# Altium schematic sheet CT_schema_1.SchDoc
size 406 x 198 mm
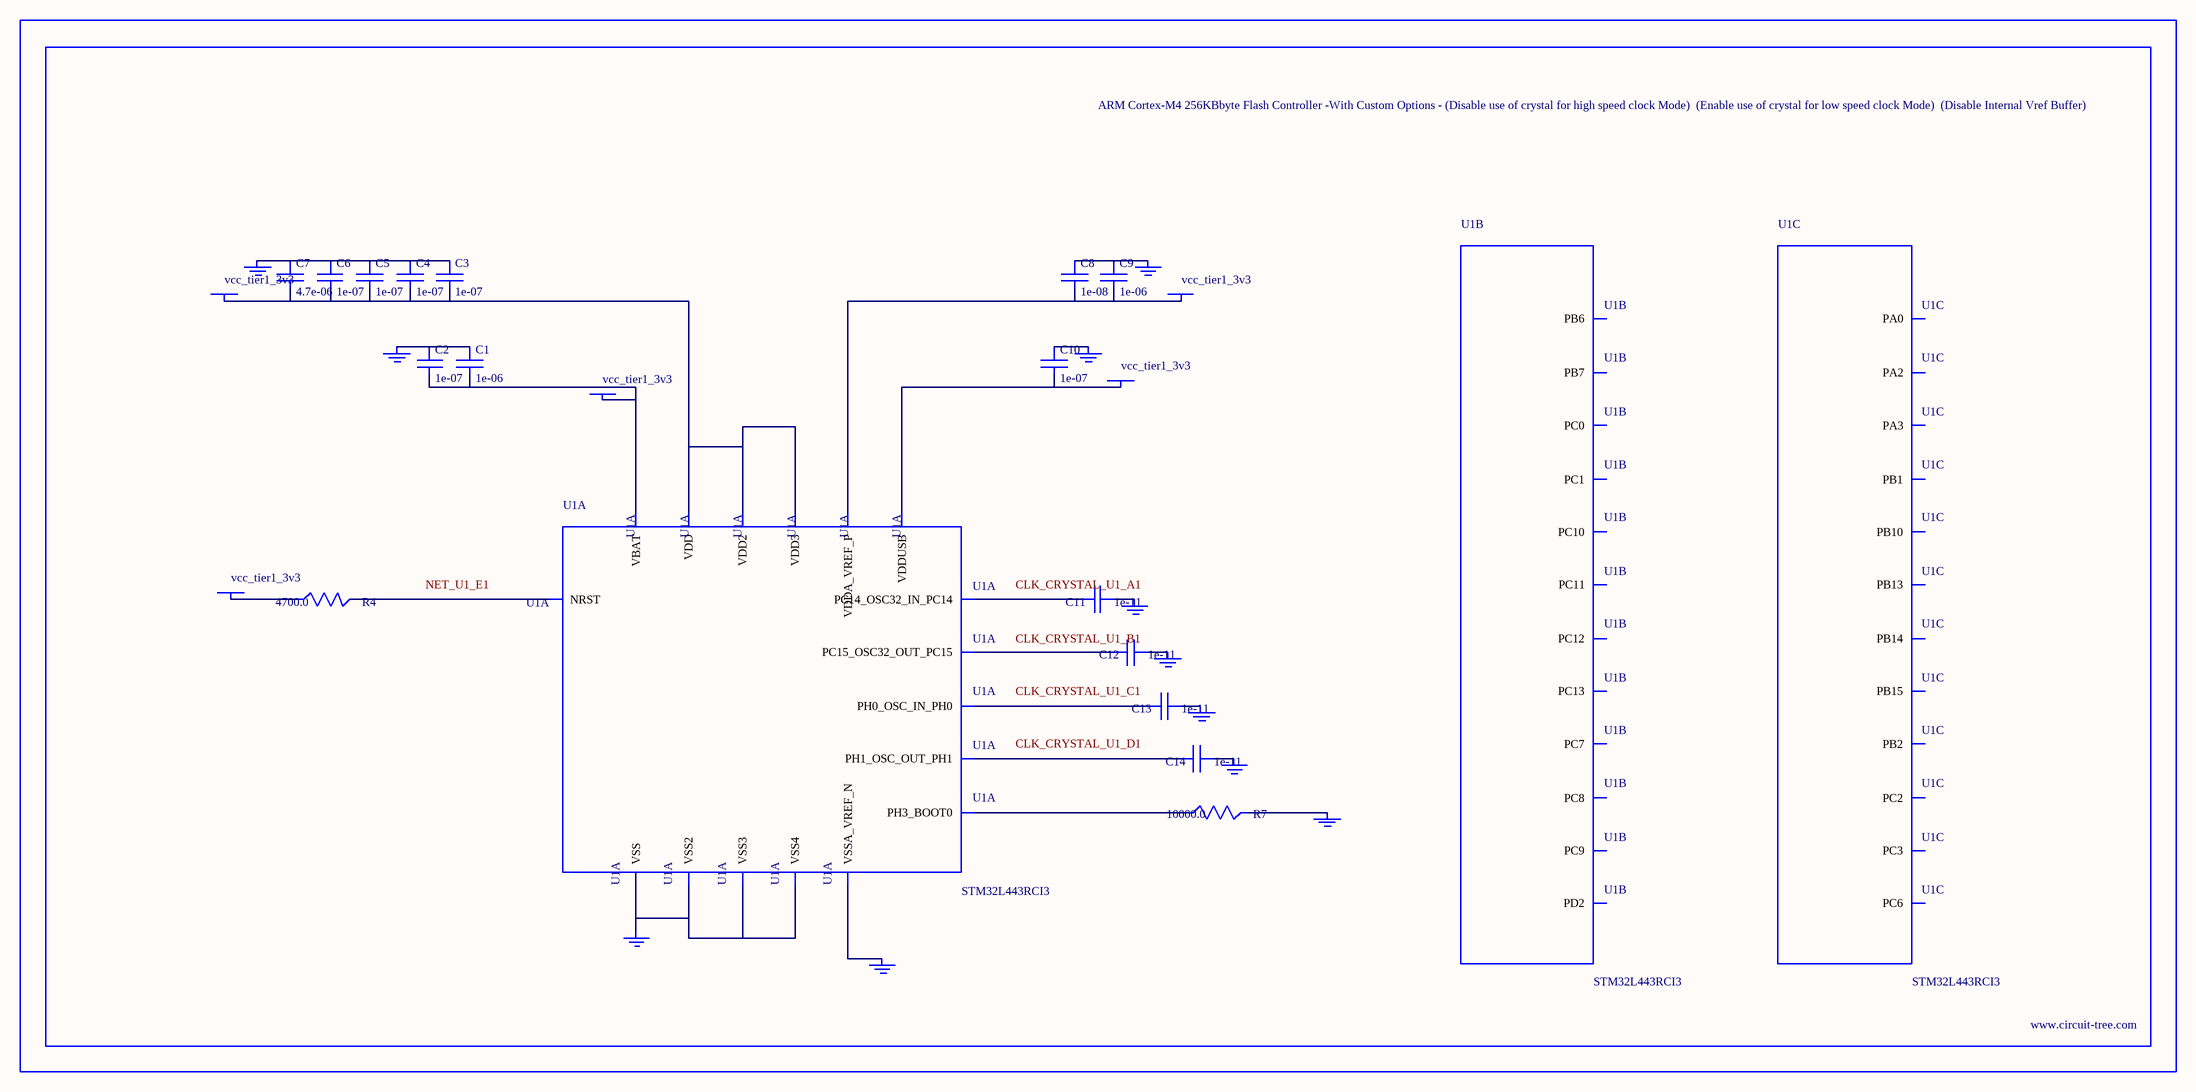
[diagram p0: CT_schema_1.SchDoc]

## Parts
BORDER0  (no value)
C1  1e-06  [C0603]
C2  1e-07  [C0603]
C3  1e-07  [C0603]
C4  1e-07  [C0603]
C5  1e-07  [C0603]
C6  1e-07  [C0603]
C7  4.7e-06  [C0603]
C8  1e-08  [C0603]
C9  1e-06  [C0603]
C10  1e-07  [C0603]
C11  1e-11  [C0402]
C12  1e-11  [C0402]
C13  1e-11  [C0402]
C14  1e-11  [C0402]
GND_INSTANCE_0_0  (no value)
GND_INSTANCE_0_1  (no value)
GND_INSTANCE_0_2  (no value)
GND_INSTANCE_0_3  (no value)
GND_INSTANCE_0_4  (no value)
GND_INSTANCE_0_5  (no value)
GND_INSTANCE_0_6  (no value)
GND_INSTANCE_0_7  (no value)
GND_INSTANCE_0_8  (no value)
GND_INSTANCE_0_9  (no value)
GND_INSTANCE_0_10  (no value)
POWER_INSTANCE_0_0  vcc_tier1_3v3
POWER_INSTANCE_0_1  vcc_tier1_3v3
POWER_INSTANCE_0_2  vcc_tier1_3v3
POWER_INSTANCE_0_3  vcc_tier1_3v3
POWER_INSTANCE_0_4  vcc_tier1_3v3
R4  4700.0  [R0603]
R7  10000.0  [R0603]
U1  STM32L443RCI3  [UFBGA64]  (parts A,B,C of 8)

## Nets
NetC1_1: C1.1 C2.1 GND_INSTANCE_0_0.0(GND)
NetC1_2: C1.2 C2.2 POWER_INSTANCE_0_0.0(PWR) U1.B2(VBAT)
NetC3_1: C3.1 C4.1 C5.1 C6.1 C7.1 GND_INSTANCE_0_1.0(GND)
NetC3_2: C3.2 C4.2 C5.2 C6.2 C7.2 POWER_INSTANCE_0_1.0(PWR) U1.D2(VDD) U1.E4(VDD2) U1.E6(VDD3)
NetC8_1: C8.1 C9.1 GND_INSTANCE_0_3.0(GND)
NetC8_2: C8.2 C9.2 POWER_INSTANCE_0_2.0(PWR) U1.H1(VDDA_VREF_P)
NetC10_1: C10.1 GND_INSTANCE_0_4.0(GND)
NetC10_2: C10.2 POWER_INSTANCE_0_3.0(PWR) U1.E5(VDDUSB)
NetC11_1: C11.1 GND_INSTANCE_0_5.0(GND)
NetC11_2: C11.2 U1.A1(PC14_OSC32_IN_PC14)
NetC12_1: C12.1 GND_INSTANCE_0_6.0(GND)
NetC12_2: C12.2 U1.B1(PC15_OSC32_OUT_PC15)
NetC13_1: C13.1 GND_INSTANCE_0_7.0(GND)
NetC13_2: C13.2 U1.C1(PH0_OSC_IN_PH0)
NetC14_1: C14.1 GND_INSTANCE_0_8.0(GND)
NetC14_2: C14.2 U1.D1(PH1_OSC_OUT_PH1)
NetGND_INSTANCE_0_2_0: GND_INSTANCE_0_2.0(GND) R7.2
NetGND_INSTANCE_0_9_0: GND_INSTANCE_0_9.0(GND) U1.F1(VSSA_VREF_N)
NetGND_INSTANCE_0_10_0: GND_INSTANCE_0_10.0(GND) U1.C2(VSS) U1.D4(VSS2) U1.D5(VSS3) U1.D6(VSS4)
NetPOWER_INSTANCE_0_4_0: POWER_INSTANCE_0_4.0(PWR) R4.1
NetR4_2: R4.2 U1.E1(NRST)
NetR7_1: R7.1 U1.B4(PH3_BOOT0)

Not connected (* = marked no-connect by the designer): U1 A2(PC13) B5(PD2) B6(PC11) B7(PC10) C3(PB7) C5(PC12) D3(PB6) D8(PC9) E2(PC1) E3(PC0) E7(PC7) E8(PC8) F2(PC2) F3(PA2) F6(PC6) F7(PB15) F8(PB14) G1(PC3) G2(PA0) G3(PA3) G5(PB1) G6(PB2) G7(PB10) G8(PB13)

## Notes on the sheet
- Labels drawn without touching a wire or pin: CLK_CRYSTAL_U1_A1, CLK_CRYSTAL_U1_B1, CLK_CRYSTAL_U1_C1, CLK_CRYSTAL_U1_D1, NET_U1_E1

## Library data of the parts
BORDER0 = BORDER_PAGE0
C1 C9 = C0603C105K3RACTU
C2-C6 C10 = 06035C104K4Z2A
C7 = GRM188R6YA475KE15D
C8 = 06035C103K4Z2A
C11-C14 = C0402C100K3GACTU
GND_INSTANCE_0_0-GND_INSTANCE_0_10 = GND
POWER_INSTANCE_0_0-POWER_INSTANCE_0_4 = PWR
R4 = RC0603JR-074K7L
R7 = RC0603JR-0710KL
